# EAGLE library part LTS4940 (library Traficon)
CT: 26/03/08: created package, 7segment display from "the bakskes behind me" (now only available from Mouser)
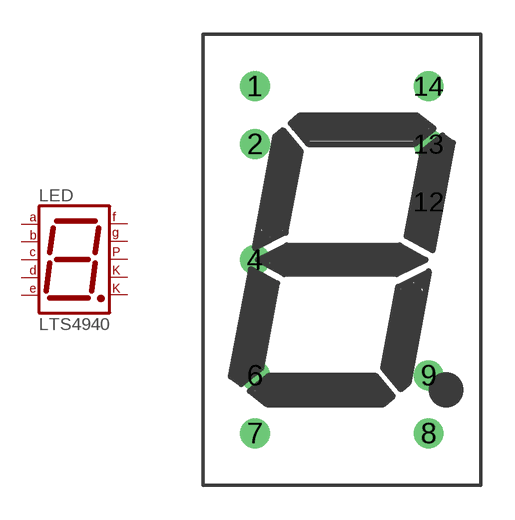
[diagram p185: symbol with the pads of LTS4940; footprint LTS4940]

Designator prefix LED

## LTS4940AHR  [LTS4940]
1  F  pas
2  G  pas
4  CK1  pas
6  E  pas
7  D  pas
8  C  pas
9  DP  pas
12  CK2  pas
13  B  pas
14  A  pas

## Footprint LTS4940 (pad centres in mm)
drill 0.8 round: 1 -5.08,5.08; 2 -5.08,2.54; 4 -5.08,-2.54; 6 -5.08,-7.62; 7 -5.08,-10.16; 8 2.54,-10.16; 9 2.54,-7.62; 12 2.54,0; 13 2.54,2.54; 14 2.54,5.08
